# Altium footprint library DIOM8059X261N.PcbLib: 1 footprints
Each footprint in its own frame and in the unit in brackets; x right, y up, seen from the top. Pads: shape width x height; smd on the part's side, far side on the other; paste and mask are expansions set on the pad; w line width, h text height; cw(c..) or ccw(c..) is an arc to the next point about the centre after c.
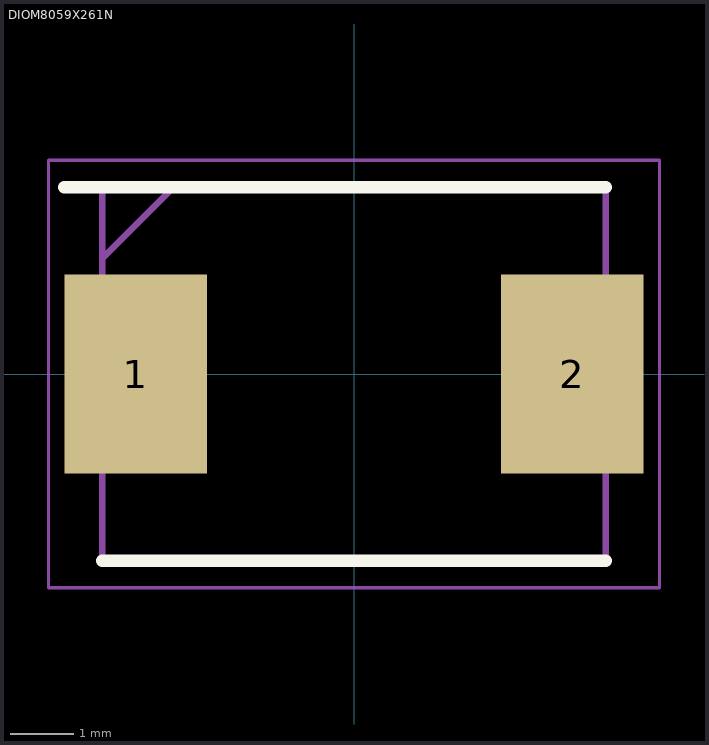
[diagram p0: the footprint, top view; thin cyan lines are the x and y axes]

## DIOM8059X261N [mm]
pads (2):
  rect 2.25x3.15 smd: 1(-3.45,0) 2(3.45,0)
Top Overlay:
  lines w0.2: -4.575,2.95 3.975,2.95 ; -3.975,-2.95 3.975,-2.95
Mechanical 15:
  lines w0.1: -3.975,1.825 -2.85,2.95 ; -3.975,-2.95 3.975,-2.95 3.975,2.95 -3.975,2.95 -3.975,-2.95
Mechanical 20:
  lines w0.05: -4.825,-3.375 4.825,-3.375 4.825,3.375 -4.825,3.375 -4.825,-3.375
